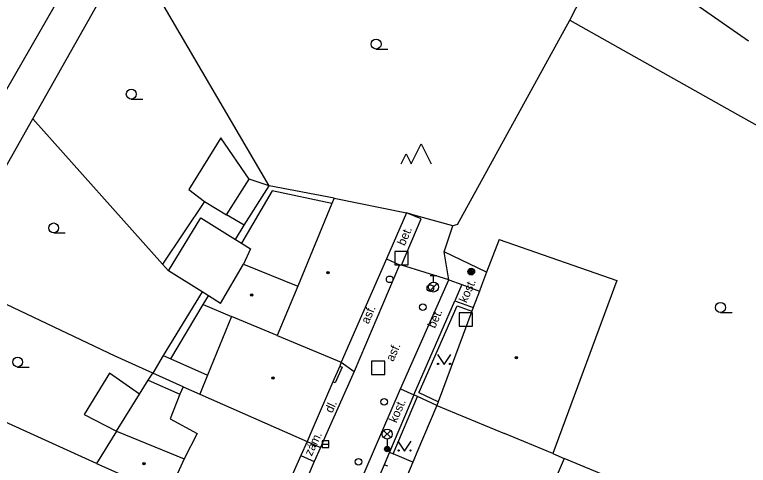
# Model space of a CAD drawing. Extents: x -598233 to -596890, y -1157848 to -1156431.
# Drawn here: x -597370.7 to -597315.5, y -1157276.1 to -1157242.2 of the extents above; entities that cross this region are included whole.
import ezdxf

# ---------------------------------------------------------------- set-up
doc = ezdxf.new("R2010")
doc.units = 0
for name, color, linetype in [('Level 10', 7, 'Continuous'), ('Level 11', 7, 'Continuous'), ('Level 25', 7, 'Continuous'), ('Level 26', 7, 'Continuous'), ('Level 27', 7, 'Continuous'), ('Level 28', 7, 'Continuous'), ('Level 31', 7, 'Continuous'), ('Level 33', 7, 'Continuous'), ('Level 36', 7, 'Continuous'), ('Level 37', 7, 'Continuous'), ('Level 39', 7, 'Continuous'), ('Level 40', 7, 'Continuous'), ('Level 5', 7, 'Continuous'), ('Level 7', 7, 'Continuous'), ('Level 8', 7, 'Continuous')]:
    doc.layers.add(name, color=color, linetype=linetype)

msp = doc.modelspace()

# ---------------------------------------------------------------- linework, layer by layer
at = {"layer": 'Level 10'}
for points in [[(-597341.76, -1157261), (-597345.17, -1157269.04)], [(-597338.06, -1157262.13), (-597341.63, -1157261.04), (-597341.76, -1157261)], [(-597361.6, -1157316.58), (-597357.53, -1157307.18), (-597350, -1157289.9699), (-597348.96, -1157289.19), (-597347.39, -1157285.61), (-597347.01, -1157282.72), (-597345.68, -1157279.62), (-597341.69, -1157270.35), (-597338.06, -1157262.13)], [(-597345.17, -1157269.04), (-597347.33, -1157273.89), (-597347.7199, -1157274.77)], [(-597347.7199, -1157274.77), (-597348.19, -1157275.81)], [(-597348.19, -1157275.81), (-597350.82, -1157282.01)]]:
    msp.add_lwpolyline(points, dxfattribs=at)
at = {"layer": 'Level 11'}
for points in [[(-597335.82, -1157229.94), (-597315.51, -1157244.14)], [(-597328.96, -1157242.59), (-597327.18, -1157239.08), (-597332.83, -1157235.2199), (-597341.39, -1157233.73), (-597361.11, -1157238.75)], [(-597362.94, -1157237.26), (-597365.85, -1157238.21), (-597400.18, -1157297.99), (-597401.46, -1157296.78), (-597403.17, -1157293.45), (-597404.09, -1157289.14), (-597403.99, -1157287.08), (-597403.6, -1157284.79), (-597402.44, -1157279.71), (-597402.24, -1157276.6599), (-597402.55, -1157272.28), (-597403.3, -1157269.39), (-597404.38, -1157266.4699), (-597406.18, -1157263.46), (-597408.4, -1157258.85), (-597409.43, -1157256.07), (-597410.15, -1157252.9099), (-597410.58, -1157244.37)], [(-597369.37, -1157250.01), (-597363.37, -1157239.37), (-597361.11, -1157238.75)], [(-597351.57, -1157255.05), (-597361.11, -1157238.75)], [(-597337.4, -1157257.98), (-597328.96, -1157242.59)], [(-597328.96, -1157242.59), (-597316.3358, -1157249.6788), (-597311.81, -1157252.2199), (-597308.52, -1157255.11), (-597308.1599, -1157277.06)], [(-597376, -1157261.78), (-597369.37, -1157250.01)], [(-597369.37, -1157250.01), (-597359.59, -1157260.96)], [(-597353.08, -1157254.56), (-597355.21, -1157251.45), (-597357.63, -1157255.33), (-597356.45, -1157256.25)], [(-597354.79, -1157257.23), (-597353.08, -1157254.56)], [(-597351.57, -1157255.05), (-597353.08, -1157254.56)], [(-597353.45, -1157258.03), (-597351.57, -1157255.05)], [(-597346.68, -1157255.99), (-597351.57, -1157255.05)], [(-597346.86, -1157256.4), (-597351.35, -1157255.44), (-597353.66, -1157259.38)], [(-597356.45, -1157256.25), (-597359.59, -1157260.96)], [(-597356.45, -1157256.25), (-597354.79, -1157257.23)], [(-597359.14, -1157261.46), (-597356.72, -1157257.47), (-597354.12, -1157259.09), (-597353.66, -1157259.38), (-597352.98, -1157259.8), (-597353.51, -1157260.96)], [(-597353.45, -1157258.03), (-597354.79, -1157257.23)], [(-597341.63, -1157261.04), (-597340.14, -1157257.55)], [(-597337.76, -1157258.08), (-597340.6, -1157257.28), (-597341.25, -1157257.1)], [(-597340.14, -1157257.55), (-597341.25, -1157257.1)], [(-597354.12, -1157259.09), (-597353.45, -1157258.03)], [(-597338.4, -1157260.04), (-597337.76, -1157258.08)], [(-597337.4, -1157257.98), (-597337.76, -1157258.08)], [(-597338.06, -1157262.13), (-597338.4, -1157260.04)], [(-597335.2199, -1157261.57), (-597338.4, -1157260.04)], [(-597342.76, -1157260.56), (-597341.76, -1157261)], [(-597359.59, -1157260.96), (-597359.14, -1157261.46)], [(-597355.23, -1157263.91), (-597353.51, -1157260.96)], [(-597360.34, -1157269.17), (-597363.17, -1157267.89), (-597376, -1157261.78)], [(-597355.23, -1157263.91), (-597356.15, -1157263.34), (-597356.63, -1157263.03), (-597359.14, -1157261.46)], [(-597338.06, -1157262.13), (-597337.07, -1157262.5)], [(-597337.07, -1157262.5), (-597337.6, -1157263.71)], [(-597337.07, -1157262.5), (-597335.76, -1157262.98)], [(-597356.63, -1157263.03), (-597359.54, -1157267.84)], [(-597358.9699, -1157268.09), (-597356.54, -1157264), (-597356.15, -1157263.34)], [(-597356.54, -1157264), (-597354.42, -1157264.89)], [(-597359.54, -1157267.84), (-597360.34, -1157269.17)], [(-597359.54, -1157267.84), (-597358.9699, -1157268.09)], [(-597358.9699, -1157268.09), (-597356.21, -1157269.31)], [(-597346.15, -1157268.35), (-597345.17, -1157269.04)], [(-597364.58, -1157275.96), (-597380.04, -1157268.94)], [(-597346.27, -1157268.63), (-597346.09, -1157268.71), (-597346.6, -1157269.9), (-597346.78, -1157269.82)], [(-597361.33, -1157270.75), (-597363.6, -1157269.17), (-597365.5, -1157272.27), (-597363.06, -1157273.53)], [(-597361.33, -1157270.75), (-597360.67, -1157269.69)], [(-597360.67, -1157269.69), (-597360.34, -1157269.17)], [(-597360.67, -1157269.69), (-597358.29, -1157270.76)], [(-597358.06, -1157270.19), (-597360.34, -1157269.17)], [(-597363.06, -1157273.53), (-597361.33, -1157270.75)], [(-597341.69, -1157270.35), (-597340.69, -1157270.79)], [(-597348.73, -1157274.32), (-597347.7199, -1157274.77)], [(-597349.19, -1157275.36), (-597348.19, -1157275.81)], [(-597340.77, -1157275.88), (-597342.25, -1157275.25)], [(-597312.81, -1157282.49), (-597329.38, -1157275.59)]]:
    msp.add_lwpolyline(points, dxfattribs=at)
at = {"layer": 'Level 25'}
for radius in [0.25, 0.2, 0.15, 0.1, 0.05]:
    msp.add_circle((-597336.37, -1157261.52), radius, dxfattribs=at)
at = {"layer": 'Level 26'}
for points in [[(-597342.12, -1157261.01), (-597341.12, -1157261.01), (-597341.12, -1157260.01), (-597342.12, -1157260.01)], [(-597337.28, -1157265.63), (-597336.28, -1157265.63), (-597336.28, -1157264.63), (-597337.28, -1157264.63)], [(-597343.88, -1157269.27), (-597342.88, -1157269.27), (-597342.88, -1157268.27), (-597343.88, -1157268.27)]]:
    msp.add_lwpolyline(points, close=True, dxfattribs=at)
at = {"layer": 'Level 27'}
msp.add_line((-597347.58, -1157274.51), (-597347.08, -1157274.51), dxfattribs=at)
msp.add_lwpolyline([(-597347.58, -1157274.76), (-597347.08, -1157274.76), (-597347.08, -1157274.26), (-597347.58, -1157274.26)], close=True, dxfattribs=at)
at = {"layer": 'Level 28'}
for p, q in [((-597339.46, -1157261.805), (-597338.96, -1157261.805)), ((-597339.21, -1157262.305), (-597339.21, -1157261.805)), ((-597339.468, -1157262.952), (-597338.938, -1157262.422))]:
    msp.add_line(p, q, dxfattribs=at)
for centre, radius in [((-597339.45, -1157262.76), 0.25), ((-597339.21, -1157262.68), 0.375), ((-597340.01, -1157264.19), 0.25), ((-597342.93, -1157271.32), 0.25), ((-597344.86, -1157275.84), 0.25)]:
    msp.add_circle(centre, radius, dxfattribs=at)
at = {"layer": 'Level 31'}
msp.add_circle((-597342.51, -1157262.1), 0.25, dxfattribs=at)
at = {"layer": 'Level 33'}
for p, q in [((-597342.965, -1157274.02), (-597342.435, -1157273.49)), ((-597342.965, -1157273.49), (-597342.435, -1157274.02)), ((-597342.7, -1157274.13), (-597342.7, -1157274.88))]:
    msp.add_line(p, q, dxfattribs=at)
for centre, radius in [((-597342.7, -1157273.755), 0.375), ((-597342.7, -1157274.88), 0.2), ((-597342.7, -1157274.88), 0.1445), ((-597342.7, -1157274.88), 0.0876)]:
    msp.add_circle(centre, radius, dxfattribs=at)
at = {"layer": 'Level 36'}
for p, q in [((-597343.53, -1157244.755), (-597342.655, -1157244.755)), ((-597361.95, -1157248.525), (-597361.075, -1157248.525)), ((-597367.79, -1157258.605), (-597366.915, -1157258.605)), ((-597317.62, -1157264.5949), (-597316.745, -1157264.5949)), ((-597370.5, -1157268.705), (-597369.625, -1157268.705))]:
    msp.add_line(p, q, dxfattribs=at)
for points in [[(-597338.92, -1157267.77), (-597338.42, -1157268.52), (-597337.92, -1157267.77)], [(-597341.89, -1157274.29), (-597341.39, -1157275.04), (-597340.89, -1157274.29)]]:
    msp.add_lwpolyline(points, dxfattribs=at)
for centre, radius in [((-597343.5301, -1157244.3799), 0.375), ((-597361.9501, -1157248.1499), 0.375), ((-597367.7901, -1157258.2299), 0.375), ((-597317.6201, -1157264.2198), 0.375), ((-597370.5001, -1157268.3299), 0.375), ((-597338.8702, -1157268.4698), 0.05), ((-597337.9708, -1157268.4698), 0.05), ((-597341.8402, -1157274.9898), 0.05), ((-597340.9408, -1157274.9898), 0.05)]:
    msp.add_circle(centre, radius, dxfattribs=at)
at = {"layer": 'Level 37'}
msp.add_lwpolyline([(-597341.65, -1157253.4), (-597341.275, -1157252.65), (-597340.9, -1157253.4), (-597340.15, -1157251.9), (-597339.4, -1157253.4)], dxfattribs=at)
at = {"layer": 'Level 39'}
for centre, radius in [((-597347.15, -1157261.59), 0.09), ((-597347.15, -1157261.59), 0.0398), ((-597352.89, -1157263.28), 0.09), ((-597352.89, -1157263.28), 0.0398), ((-597332.98, -1157267.99), 0.09), ((-597332.98, -1157267.99), 0.0398), ((-597351.29, -1157269.54), 0.09), ((-597351.29, -1157269.54), 0.0398), ((-597360.99, -1157275.99), 0.09), ((-597360.99, -1157275.99), 0.0398)]:
    msp.add_circle(centre, radius, dxfattribs=at)
at = {"layer": 'Level 5'}
for points in [[(-597346.86, -1157256.4), (-597349.43, -1157262.62)], [(-597346.68, -1157255.99), (-597346.86, -1157256.4)], [(-597346.68, -1157255.99), (-597341.25, -1157257.1)], [(-597341.25, -1157257.1), (-597342.76, -1157260.56)], [(-597334.26, -1157259.1), (-597335.2199, -1157261.57)], [(-597334.26, -1157259.1), (-597325.42, -1157262.18)], [(-597342.76, -1157260.56), (-597346.15, -1157268.35)], [(-597353.51, -1157260.96), (-597349.43, -1157262.62)], [(-597335.2199, -1157261.57), (-597335.6, -1157262.57)], [(-597325.42, -1157262.18), (-597330.24, -1157275.23)], [(-597349.43, -1157262.62), (-597350.9699, -1157266.34)], [(-597335.76, -1157262.98), (-597336.2199, -1157264.2199)], [(-597335.6, -1157262.57), (-597335.76, -1157262.98)], [(-597336.32, -1157264.5), (-597338.85, -1157271.33)], [(-597336.2199, -1157264.2199), (-597336.32, -1157264.5)], [(-597354.42, -1157264.89), (-597356.21, -1157269.31)], [(-597350.9699, -1157266.34), (-597354.42, -1157264.89)], [(-597350.9699, -1157266.34), (-597346.15, -1157268.35)], [(-597346.15, -1157268.35), (-597346.27, -1157268.63)], [(-597346.27, -1157268.63), (-597346.78, -1157269.82)], [(-597356.21, -1157269.31), (-597356.79, -1157270.75)], [(-597358.06, -1157270.19), (-597358.29, -1157270.76)], [(-597358.06, -1157270.19), (-597356.79, -1157270.75)], [(-597346.78, -1157269.82), (-597348.37, -1157273.49), (-597348.73, -1157274.32)], [(-597358.29, -1157270.76), (-597359.03, -1157272.6)], [(-597356.79, -1157270.75), (-597348.73, -1157274.32)], [(-597338.85, -1157271.33), (-597338.95, -1157271.61)], [(-597338.95, -1157271.61), (-597340.46, -1157275.15), (-597340.69, -1157275.7), (-597340.77, -1157275.88)], [(-597338.95, -1157271.61), (-597333.87, -1157273.7199)], [(-597359.03, -1157272.6), (-597356.99, -1157273.7199)], [(-597363.06, -1157273.53), (-597364.58, -1157275.96)], [(-597363.06, -1157273.53), (-597357.98, -1157275.62)], [(-597356.99, -1157273.7199), (-597357.98, -1157275.62)], [(-597330.24, -1157275.23), (-597333.87, -1157273.7199)], [(-597348.73, -1157274.32), (-597349.19, -1157275.36)], [(-597330.24, -1157275.23), (-597329.38, -1157275.59)], [(-597357.98, -1157275.62), (-597359.19, -1157278.34)], [(-597349.19, -1157275.36), (-597351.93, -1157281.54)], [(-597329.38, -1157275.59), (-597330.77, -1157278.82)], [(-597364.58, -1157275.96), (-597361.28, -1157277.42)], [(-597340.77, -1157275.88), (-597341.17, -1157276.82)]]:
    msp.add_lwpolyline(points, dxfattribs=at)
at = {"layer": 'Level 7'}
for points in [[(-597340.69, -1157270.79), (-597337.6, -1157263.71)], [(-597340.28, -1157270.59), (-597337.44, -1157264.09), (-597336.32, -1157264.5)], [(-597337.6, -1157263.71), (-597336.2199, -1157264.2199)], [(-597340.69, -1157270.79), (-597342.53, -1157275.13)], [(-597340.42, -1157270.92), (-597340.69, -1157270.79)], [(-597338.85, -1157271.33), (-597340.3, -1157270.64), (-597340.28, -1157270.59)], [(-597342.25, -1157275.25), (-597340.42, -1157270.92)], [(-597338.95, -1157271.61), (-597340.42, -1157270.92)], [(-597342.53, -1157275.13), (-597342.25, -1157275.25)], [(-597342.93, -1157276.07), (-597344.69, -1157280.15)], [(-597342.65, -1157276.18), (-597342.93, -1157276.07)]]:
    msp.add_lwpolyline(points, dxfattribs=at)
at = {"layer": 'Level 8'}
msp.add_lwpolyline([(-597342.53, -1157275.13), (-597342.93, -1157276.07)], dxfattribs=at)

# ---------------------------------------------------------------- texts
at = {"layer": 'Level 40'}
for s, rotation, p in [('bet.', 66.78474, (-597341.38, -1157259.62)), ('kost.', 66.54547, (-597336.73, -1157263.92)), ('asf.', 66.27497, (-597344.11, -1157265.51)), ('bet.', 66.54547, (-597339.1, -1157265.84)), ('asf.', 66.27497, (-597342.24, -1157268.34)), ('kost.', 66.73438, (-597342, -1157272.96)), ('dl.', 64.93253, (-597346.84, -1157272.22)), ('zám.', 64.93253, (-597348.38, -1157275.46))]:
    msp.add_text(s, height=0.65, rotation=rotation, dxfattribs=at).set_placement(p)

doc.saveas('drawing.dxf')
